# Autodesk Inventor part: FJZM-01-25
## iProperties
Author: Malcolm
Shininess: 31.0
PropertySet Name: _Private Model Information
Created: 2001-03
Part Number: FJZM-01-25
Description: DryLin Round Flange
Document SubType Name: Modeling
Designer: Malcolm
Control State: 0
Master: False
Checked Out: False
PropertySet Name: Design Tracking Control
Density: 0.0
Volumn: 0.0
Area: 0.0
PropertySet Name: Model Information
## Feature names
1. Revolution1
2. Extrusion1
3. Circular Pattern1
4. Extrusion2
5. Revolution2
6. Chamfer1
7. Extrusion4
8. Hole2
9. Extrusion3
